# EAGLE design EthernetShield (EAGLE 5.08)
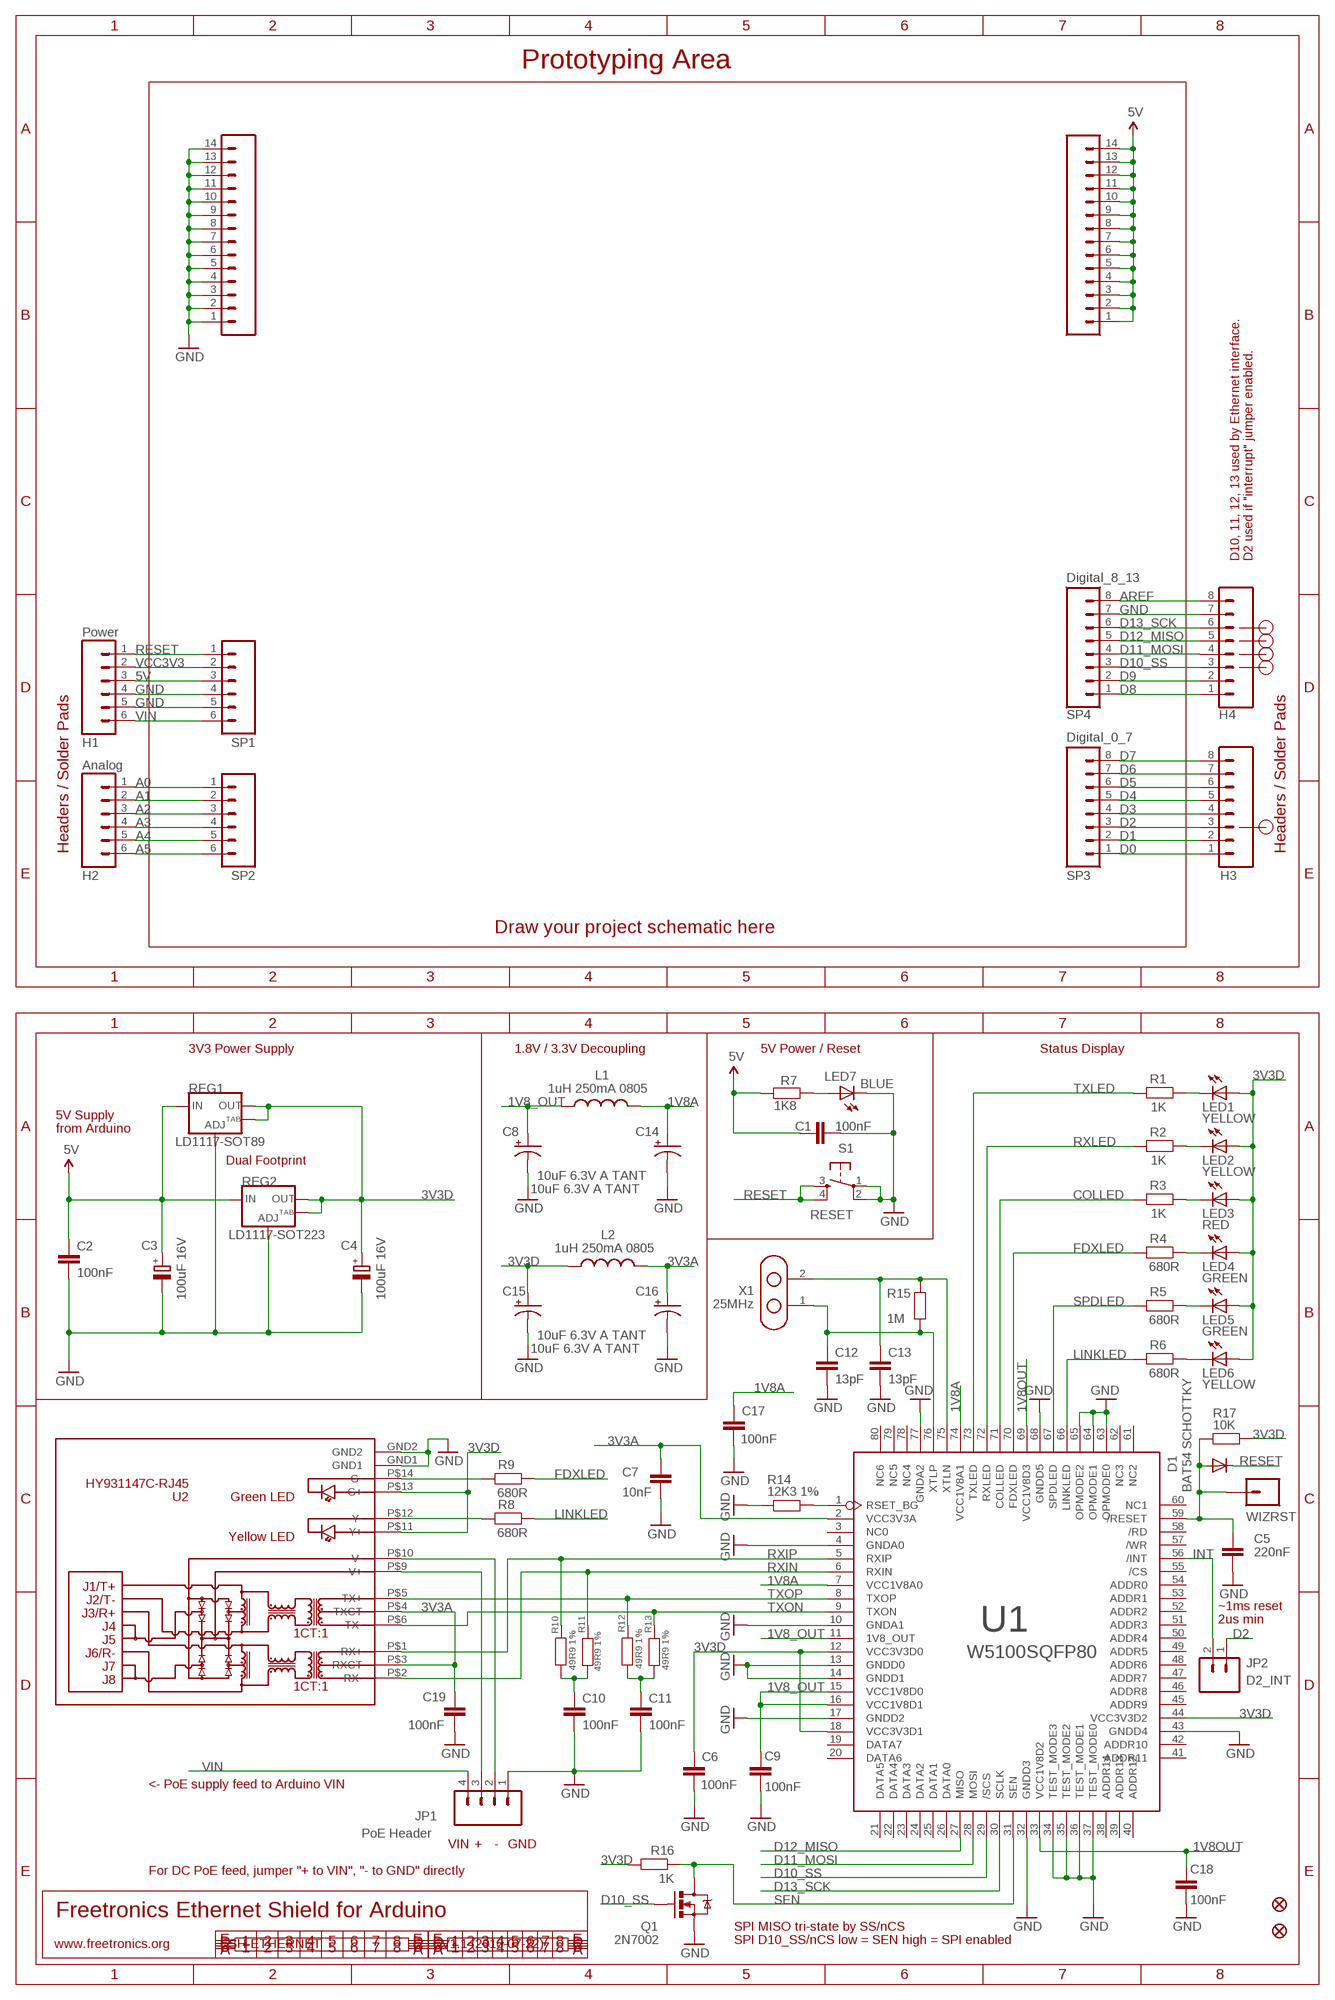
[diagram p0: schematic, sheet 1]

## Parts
C1  100nF  CAP0603  [0603]
C2  100nF  CAP0603  [0603]
C3  100uF 16V  CPOL-EUD  [PANASONIC_D]
C4  100uF 16V  CPOL-EUD  [PANASONIC_D]
C5  220nF  CAP0603  [0603]
C6  100nF  CAP0603  [0603]
C7  10nF  CAP0603  [0603]
C8  10uF 6.3V A TANT  CAP_POL1206  [EIA3216]
C9  100nF  CAP0603  [0603]
C10  100nF  CAP0603  [0603]
C11  100nF  CAP0603  [0603]
C12  13pF  CAP0603  [0603]
C13  13pF  CAP0603  [0603]
C14  10uF 6.3V A TANT  CAP_POL1206  [EIA3216]
C15  10uF 6.3V A TANT  CAP_POL1206  [EIA3216]
C16  10uF 6.3V A TANT  CAP_POL1206  [EIA3216]
C17  100nF  CAP0603  [0603]
C18  100nF  CAP0603  [0603]
C19  100nF  CAP0603  [0603]
D1  BAT54 SCHOTTKY  DIODESOT23  [SOT23-3]
H1  Power  M06SIP  [1X06]
H2  Analog  M06SIP  [1X06]
H3  Digital_0_7  M08  [1X08]
H4  Digital_8_13  M08  [1X08]
JP1  PoE Header  M04PTH  [1X04]
JP2  D2_INT  M02PTH  [1X02]
L1  1uH 250mA 0805  L-USL2012C  [L2012C]
L2  1uH 250mA 0805  L-USL2012C  [L2012C]
LED1  YELLOW  LED0603  [LED-0603]
LED2  YELLOW  LED0603  [LED-0603]
LED3  RED  LED0603  [LED-0603]
LED4  GREEN  LED0603  [LED-0603]
LED5  GREEN  LED0603  [LED-0603]
LED6  YELLOW  LED0603  [LED-0603]
LED7  BLUE  LED0603  [LED-0603]
PADS_5V  M14  [1X14]
PADS_GND  M14  [1X14]
Q1  2N7002  MOSFET-NCHANNELSMD  [SOT23-3]
R1  1K  RESISTOR0603  [0603]
R2  1K  RESISTOR0603  [0603]
R3  1K  RESISTOR0603  [0603]
R4  680R  RESISTOR0603  [0603]
R5  680R  RESISTOR0603  [0603]
R6  680R  RESISTOR0603  [0603]
R7  1K8  RESISTOR0603  [0603]
R8  680R  RESISTOR0603  [0603]
R9  680R  RESISTOR0603  [0603]
R10  49R9 1%  RESISTOR0603  [0603]
R11  49R9 1%  RESISTOR0603  [0603]
R12  49R9 1%  RESISTOR0603  [0603]
R13  49R9 1%  RESISTOR0603  [0603]
R14  12K3 1%  RESISTOR0603  [0603]
R15  1M  RESISTOR0603  [0603]
R16  1K  RESISTOR0603  [0603]
R17  10K  RESISTOR0603  [0603]
REG1  LD1117-SOT89  V_REG_LM1117SOT89  [SOT89]
REG2  LD1117-SOT223  V_REG_LM1117SOT223  [SOT223]
S1  RESET  TAC_SWITCHSMD  [TACTILE_SWITCH_SMD]
SP1  Power  M06SIP  [1X06]
SP2  Analog  M06SIP  [1X06]
SP3  Digital_0_7  M08  [1X08]
SP4  Digital_8_13  M08  [1X08]
U1  W5100SQFP80  [SQFP80]
U2  HY931147C-RJ45  [HY931147C]
U$6  FIDUCIAL1X2.5  [FIDUCIAL-1X2.5]
U$8  FIDUCIAL1X2.5  [FIDUCIAL-1X2.5]
WIZRST  M01PTH  [1X01]
X1  25MHz  XTL_B  [XTL_B]

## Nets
1V8_OUT: C8.A(+) C9.1 L1.1 U1.11(1V8_OUT) U1.15(VCC1V8D0) U1.16(VCC1V8D1)
1V8A: C14.A(+) C17.1 L1.2 U1.7(VCC1V8A0) U1.74(VCC1V8A1)
1V8OUT: C18.1 U1.33(VCC1V8D2) U1.69(VCC1V8D3)
3V3A: C7.1 C16.A(+) C19.1 L2.2 U1.2(VCC3V3A) U2.P$3(RXCT) U2.P$4(TXCT)
3V3D: C4.+ C6.1 C15.A(+) L2.1 LED1.A LED2.A LED3.A LED4.A LED5.A LED6.A R16.2 R17.1 REG1.2(OUT) REG1.4(OUT) REG2.2(OUT) REG2.4(OUT) U1.12(VCC3V3D0) U1.18(VCC3V3D1) U1.44(VCC3V3D2) U2.P$11(Y+) U2.P$13(G+)
5V: C1.1 C2.1 C3.+ H1.3 PADS_5V.1 PADS_5V.2 PADS_5V.3 PADS_5V.4 PADS_5V.5 PADS_5V.6 PADS_5V.7 PADS_5V.8 PADS_5V.9 PADS_5V.10 PADS_5V.11 PADS_5V.12 PADS_5V.13 PADS_5V.14 R7.1 REG1.3(IN) REG2.3(IN) SP1.3
A0: H2.1 SP2.1
A1: H2.2 SP2.2
A2: H2.3 SP2.3
A3: H2.4 SP2.4
A4: H2.5 SP2.5
A5: H2.6 SP2.6
AREF: H4.8 SP4.8
COLLED: R3.2 U1.71(COLLED)
D0: H3.1 SP3.1
D1: H3.2 SP3.2
D2: H3.3 JP2.1 SP3.3
D3: H3.4 SP3.4
D4: H3.5 SP3.5
D5: H3.6 SP3.6
D6: H3.7 SP3.7
D7: H3.8 SP3.8
D8: H4.1 SP4.1
D9: H4.2 SP4.2
D10_SS: H4.3 Q1.1(G) SP4.3 U1.29(/SCS)
D11_MOSI: H4.4 SP4.4 U1.28(MOSI)
D12_MISO: H4.5 SP4.5 U1.27(MISO)
D13_SCK: H4.6 SP4.6 U1.30(SCLK)
FDXLED: R4.2 R9.1 U1.70(FDXLED)
GND: C1.2 C2.2 C3.- C4.- C5.2 C6.2 C7.2 C8.C(-) C9.2 C10.2 C11.2 C12.2 C13.2 C14.C(-) C15.C(-) C16.C(-) C17.2 C18.2 C19.2 H1.4 H1.5 H4.7 JP1.1 LED7.C PADS_GND.1 PADS_GND.2 PADS_GND.3 PADS_GND.4 PADS_GND.5 PADS_GND.6 PADS_GND.7 PADS_GND.8 PADS_GND.9 PADS_GND.10 PADS_GND.11 PADS_GND.12 PADS_GND.13 PADS_GND.14 Q1.2(S) R14.1 REG1.1(ADJ) REG2.1(ADJ) S1.1 S1.2 SP1.4 SP1.5 SP4.7 U1.4(GNDA0) U1.10(GNDA1) U1.13(GNDD0) U1.14(GNDD1) U1.17(GNDD2) U1.32(GNDD3) U1.34(TEST_MODE3) U1.35(TEST_MODE2) U1.36(TEST_MODE1) U1.37(TEST_MODE0) U1.43(GNDD4) U1.63(OPMODE0) U1.64(OPMODE1) U1.65(OPMODE2) U1.68(GNDD5) U1.77(GNDA2) U2.GND1 U2.GND2
INT: JP2.2 U1.56(/INT)
LINKLED: R6.2 R8.1 U1.66(LINKLED)
N$1: C11.1 R12.1 R13.2
N$67: R9.2 U2.P$14(G-)
N$68: JP1.3 U2.P$9(V+)
N$69: JP1.2 U2.P$10(V-)
N$70: C5.1 D1.1(A) R17.2 U1.59(/RESET) WIZRST.1
N$131: LED7.A R7.2
N$321: C10.1 R10.1 R11.2
N$322: R14.2 U1.1(RSET_BG)
N$323: LED5.C R5.1
N$325: LED6.C R6.1
N$327: LED4.C R4.1
N$328: LED3.C R3.1
N$329: LED2.C R2.1
N$330: LED1.C R1.1
N$332: R8.2 U2.P$12(Y-)
RESET: D1.3(C) H1.1 S1.3 S1.4 SP1.1
RXIN: R11.1 U1.6(RXIN) U2.P$2(RX-)
RXIP: R10.2 U1.5(RXIP) U2.P$1(RX+)
RXLED: R2.2 U1.72(RXLED)
SEN: Q1.3(D) R16.1 U1.31(SEN)
SPDLED: R5.2 U1.67(SPDLED)
TXLED: R1.2 U1.73(TXLED)
TXON: R13.1 U1.9(TXON) U2.P$6(TX-)
TXOP: R12.2 U1.8(TXOP) U2.P$5(TX+)
VCC3V3: H1.2 SP1.2
VIN: H1.6 JP1.4 SP1.6
XTLN: C13.1 R15.2 U1.75(XTLN) X1.2
XTLP: C12.1 R15.1 U1.76(XTLP) X1.1
Unconnected: U1.3(NC0) U1.19(DATA7) U1.20(DATA6) U1.21(DATA5) U1.22(DATA4) U1.23(DATA3) U1.24(DATA2) U1.25(DATA1) U1.26(DATA0) U1.38(ADDR14) U1.39(ADDR13) U1.40(ADDR12) U1.41(ADDR11) U1.42(ADDR10) U1.45(ADDR9) U1.46(ADDR8) U1.47(ADDR7) U1.48(ADDR6) U1.49(ADDR5) U1.50(ADDR4) U1.51(ADDR3) U1.52(ADDR2) U1.53(ADDR1) U1.54(ADDR0) U1.55(/CS) U1.57(/WR) U1.58(/RD) U1.60(NC1) U1.61(NC2) U1.62(NC3) U1.78(NC4) U1.79(NC5) U1.80(NC6)

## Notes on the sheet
- Prototyping Area
- D10, 11, 12, 13 used by Ethernet interface. | D2 used if "interrupt" jumper enabled.
- Headers / Solder Pads | Headers / Solder Pads
- Draw your project schematic here
- 3V3 Power Supply | 1.8V / 3.3V Decoupling | 5V Power / Reset | Status Display
- 5V Supply
- from Arduino
- Dual Footprint
- ~1ms reset
- 2us min
- <- PoE supply feed to Arduino VIN
- VIN | + | - | GND
- For DC PoE feed, jumper "+ to VIN", "- to GND" directly
- Freetronics Ethernet Shield for Arduino
- SPI MISO tri-state by SS/nCS
- SPI D10_SS/nCS low = SEN high = SPI enabled
- www.freetronics.org | SH-ETHERNET | V1.1 (2010-07-22)

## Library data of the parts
C1 C2 C5-C7 C9-C13 C17-C19 = freetronics:CAP: Capacitor
C3 C4 = rcl:CPOL-EU: POLARIZED CAPACITOR, European symbol
C8 C14-C16 = freetronics:CAP_POL: Capacitor Polarized
D1 = freetronics:DIODE: Diode
H1 H2 SP1 SP2 = freetronics:M06: Header 6 Standard 6-pin 0.1" header. Use with straight break away headers (SKU : PRT-00116), right angle break away headers (PRT-00553), swiss pins (PRT-00743), machine pins (PRT-00117), and female headers (PRT-00115). Molex polarized connector foot print use with SKU : PRT-08094 with associated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
H3 H4 SP3 SP4 = freetronics:M08: Header 8 Standard 8-pin 0.1" header. Use with straight break away headers (SKU : PRT-00116), right angle break away headers (PRT-00553), swiss pins (PRT-00743), machine pins (PRT-00117), and female headers (PRT-00115).
JP1 = freetronics:M04: Header 4 Standard 4-pin 0.1" header. Use with straight break away headers (SKU : PRT-00116), right angle break away headers (PRT-00553), swiss pins (PRT-00743), machine pins (PRT-00117), and female headers (PRT-00115). Molex polarized connector foot print use with SKU : PRT-08231 with associated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
JP2 = freetronics:M02: Header 2
L1 L2 = rcl:L-US: INDUCTOR, American symbol
LED1-LED7 = freetronics:LED: LEDs
PADS_5V PADS_GND = freetronics:M14: Header 14 Standard 14-pin 0.1" header. Use with straight break away headers (SKU : PRT-00116), right angle break away headers (PRT-00553), swiss pins (PRT-00743), machine pins (PRT-00117), and female headers (PRT-00115).
Q1 = freetronics:MOSFET-NCHANNEL
R1-R17 = freetronics:RESISTOR: Resistor
REG1 REG2 = freetronics:V_REG_LM1117: Voltage Regulator LD1117 Adjustable low-dropout voltage regulator available in SOT89 and SOT223 SMT packages.
S1 = freetronics:TAC_SWITCH: Momentary Switch Button commonly used for reset or general input. Spark Fun Electronics SKU : COM-00097
U1 = freetronics-marc:W5100: WIZnet W5100
U2 = freetronics-jon:HY931147C
U$6 U$8 = freetronics:FIDUCIAL: Fiducial Alignment Points
WIZRST = freetronics:M01: Header 1
X1 = CPT_CJ:XTL_B

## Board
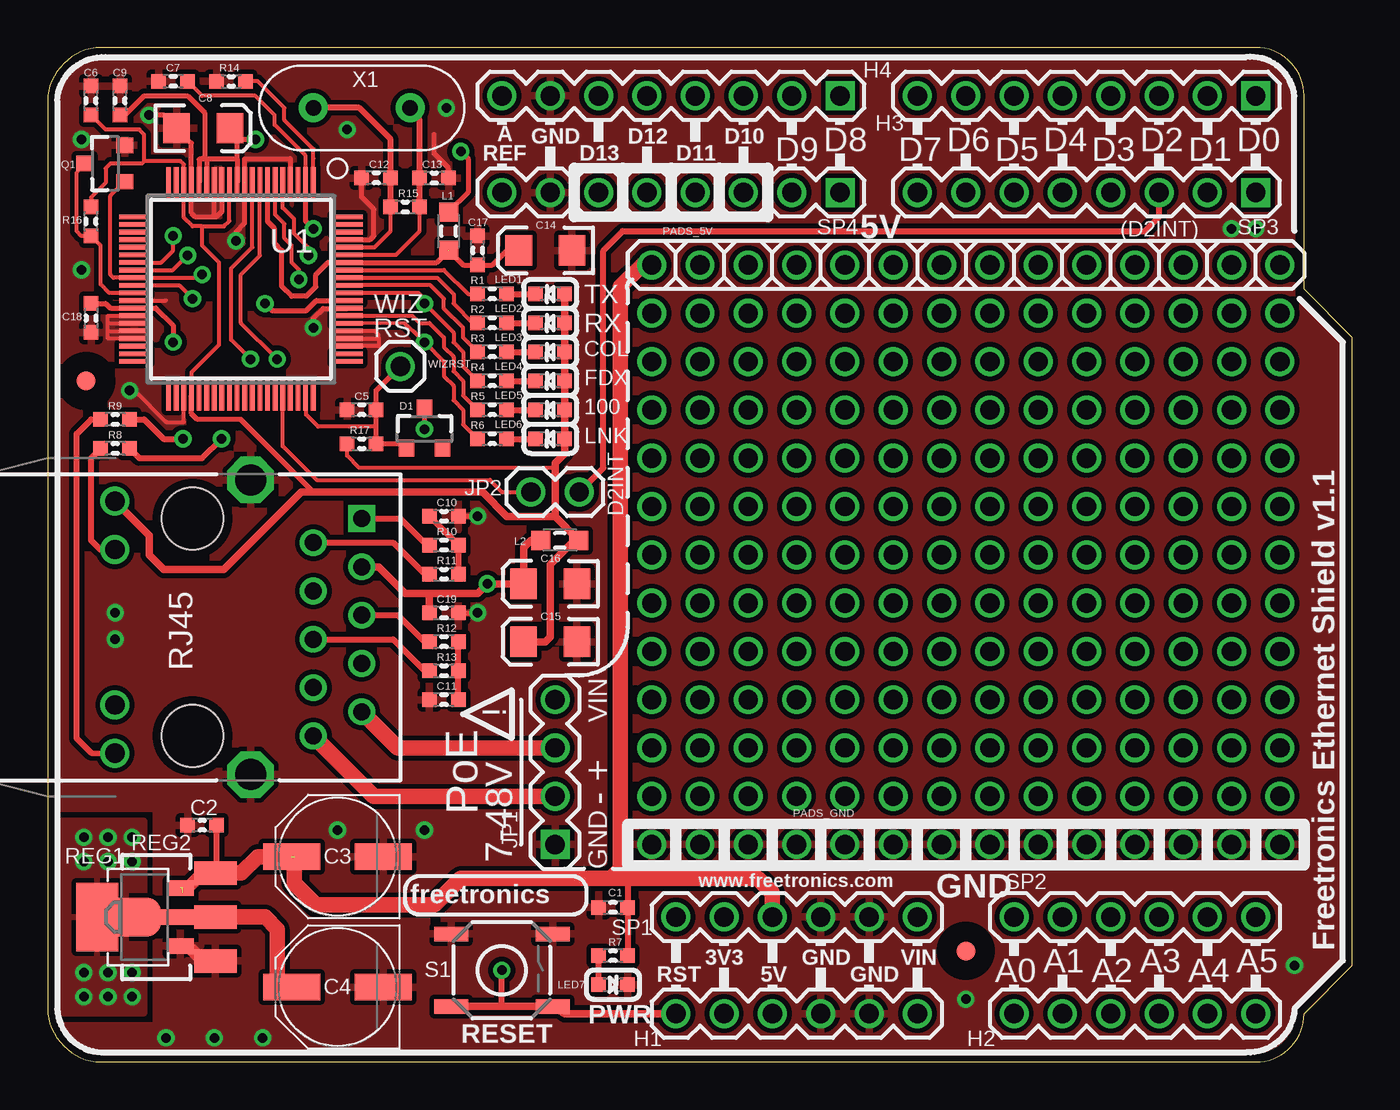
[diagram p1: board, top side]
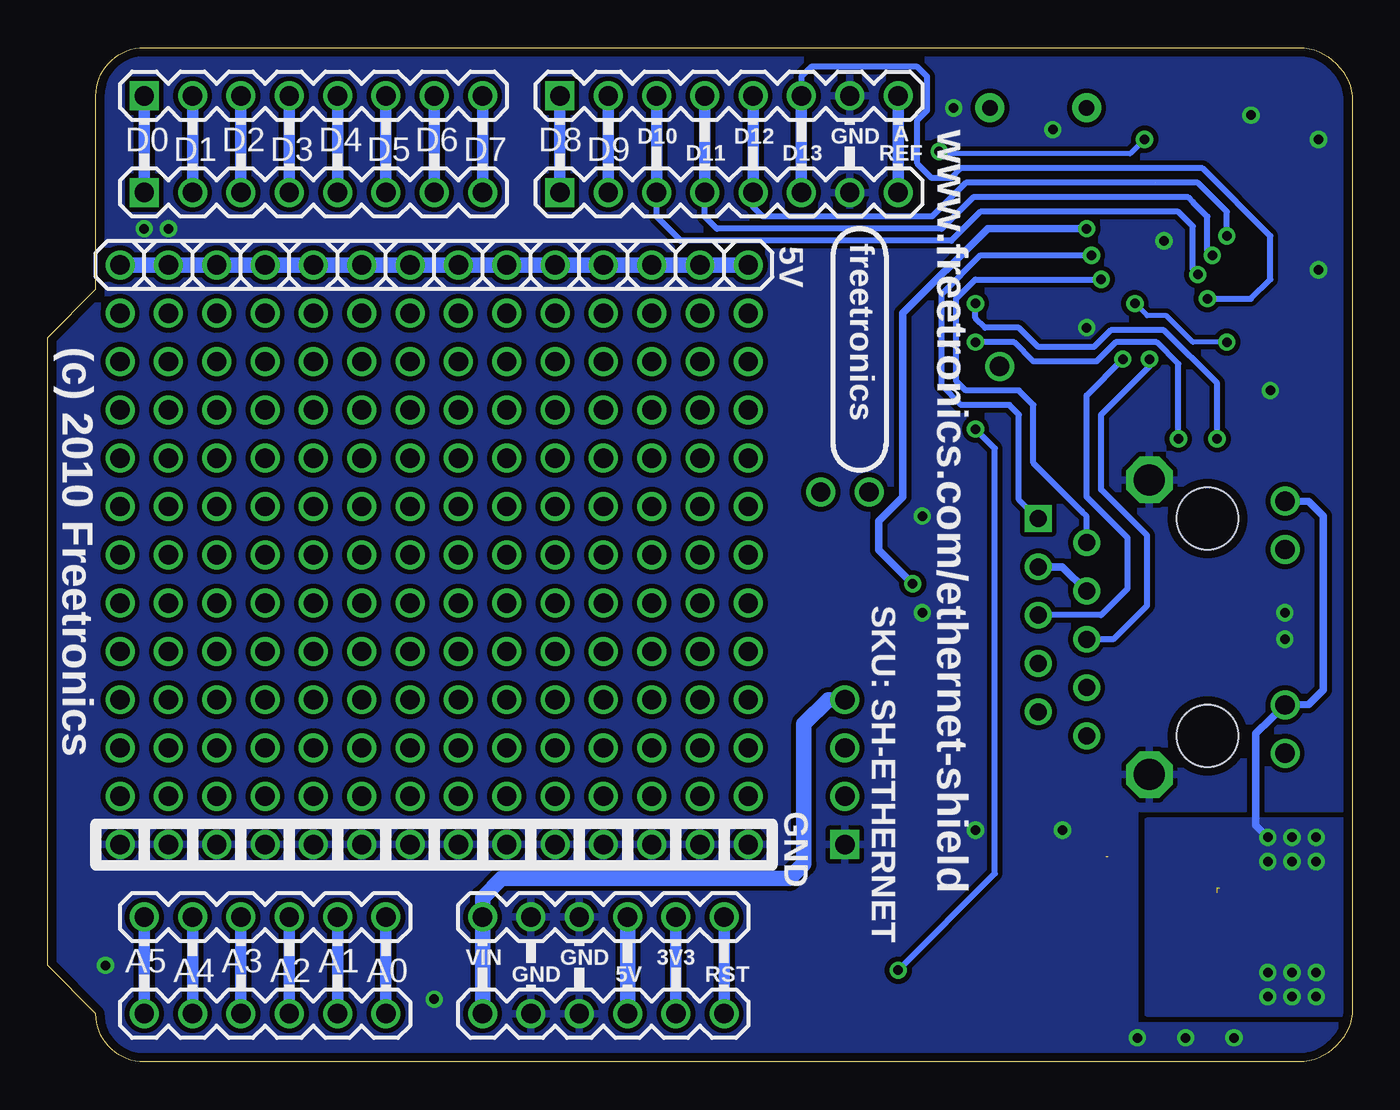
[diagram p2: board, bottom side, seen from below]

Size 68.58 x 53.34 mm. Coordinates in mm from the lower left corner, seen from the top.
Outline: 0,2.54 arc74 2.54,0 63.5,0 arc90 66.04,2.54 68.58,5.08 68.58,38.1 66.04,40.64 66.04,50.8 arc90 63.5,53.34 2.54,53.34 arc74 0,50.8 0,2.54
Copper layers (1*16): Top 0.035mm / dielectric 1.5mm / Bottom 0.035mm
Design rules "default *": minimum track width 8mil, minimum drill 18mil, track to track 10mil, track to pad 10mil, pad to pad 10mil, via to via 10mil, smd to smd 8mil, copper to edge 18mil, drill to drill 8mil, minimum pad ring 10mil, minimum via ring 8mil, stop-mask expansion 4mil, vias tented up to drill 25mil, thermal gap 10mil
tRestrict: area 1,34.8 to 3,36.8; area 47.2,4.8 to 49.3,6.9

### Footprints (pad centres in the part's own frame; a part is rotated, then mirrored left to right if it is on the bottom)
0603 = smd 0.762 x 0.762: 1 -0.762,0; 2 0.762,0
PANASONIC_D = smd 3 x 1.4: + 2.4,0; - -2.4,0
EIA3216 = smd 1.4 x 1.6: A 1.4,0; C -1.4,0
SOT23-3 = smd 0.8 x 0.9: 1 -0.95,-1; 2 0.95,-1; 3 0,1.1
1X06 = drill 1.016 round: 1 0,0; 2 2.54,0; 3 5.08,0; 4 7.62,0; 5 10.16,0; 6 12.7,0
1X08 = drill 1.016 square: 1 0,0 | drill 1.016 round: 2 2.54,0; 3 5.08,0; 4 7.62,0; 5 10.16,0; 6 12.7,0; 7 15.24,0; 8 17.78,0
1X04 = drill 1.016 square: 1 0,0 | drill 1.016 round: 2 2.54,0; 3 5.08,0; 4 7.62,0
1X02 = drill 1.016 round: 1 0,0; 2 2.54,0
L2012C = smd 1 x 1: 1 -1,0; 2 1,0
LED-0603 = smd 0.762 x 0.762: A -0.762,0; C 0.762,0
1X14 = drill 1.016 round: 1 0,0; 2 2.54,0; 3 5.08,0; 4 7.62,0; 5 10.16,0; 6 12.7,0; 7 15.24,0; 8 17.78,0; 9 20.32,0; 10 22.86,0; 11 25.4,0; 12 27.94,0; 13 30.48,0; 14 33.02,0
SOT89 = smd 0.8 x 1.4: 1 -1.524,-1.905; 3 1.524,-1.905 | smd 0.8 x 1.9: 2 0,-1.651 | smd 2.032 x 3.65: 4 0,0.94
SOT223 = smd 1.219 x 2.235: 1 -2.311,-3.099; 2 0,-3.099; 3 2.311,-3.099 | smd 3.6 x 2.2: 4 0,3.099
TACTILE_SWITCH_SMD = smd 1.778 x 0.762: 1 -2.667,1.905; 2 2.667,1.905; 3 -2.667,-1.905; 4 2.667,-1.905
SQFP80 = smd 1.6 x 0.25: 1 -5.6,3.8; 2 -5.6,3.4; 3 -5.6,3; 4 -5.6,2.6; 5 -5.6,2.2; 6 -5.6,1.8; 7 -5.6,1.4; 8 -5.6,1; 9 -5.6,0.6; 10 -5.6,0.2; 11 -5.6,-0.2; 12 -5.6,-0.6; 13 -5.6,-1; 14 -5.6,-1.4; 15 -5.6,-1.8; 16 -5.6,-2.2; 17 -5.6,-2.6; 18 -5.6,-3; 19 -5.6,-3.4; 20 -5.6,-3.8; 41 5.6,-3.8; 42 5.6,-3.4; 43 5.6,-3; 44 5.6,-2.6; 45 5.6,-2.2; 46 5.6,-1.8; 47 5.6,-1.4; 48 5.6,-1; 49 5.6,-0.6; 50 5.6,-0.2; 51 5.6,0.2; 52 5.6,0.6; 53 5.6,1; 54 5.6,1.4; 55 5.6,1.8; 56 5.6,2.2; 57 5.6,2.6; 58 5.6,3; 59 5.6,3.4; 60 5.6,3.8 | smd 0.25 x 1.6: 21 -3.8,-5.6; 22 -3.4,-5.6; 23 -3,-5.6; 24 -2.6,-5.6; 25 -2.2,-5.6; 26 -1.8,-5.6; 27 -1.4,-5.6; 28 -1,-5.6; 29 -0.6,-5.6; 30 -0.2,-5.6; 31 0.2,-5.6; 32 0.6,-5.6; 33 1,-5.6; 34 1.4,-5.6; 35 1.8,-5.6; 36 2.2,-5.6; 37 2.6,-5.6; 38 3,-5.6; 39 3.4,-5.6; 40 3.8,-5.6; 61 3.8,5.6; 62 3.4,5.6; 63 3,5.6; 64 2.6,5.6; 65 2.2,5.6; 66 1.8,5.6; 67 1.4,5.6; 68 1,5.6; 69 0.6,5.6; 70 0.2,5.6; 71 -0.2,5.6; 72 -0.6,5.6; 73 -1,5.6; 74 -1.4,5.6; 75 -1.8,5.6; 76 -2.2,5.6; 77 -2.6,5.6; 78 -3,5.6; 79 -3.4,5.6; 80 -3.8,5.6
HY931147C = drill 1.63 octagon: GND1 3.05,7.745; GND2 3.05,-7.745 | drill 0.9 square: P$1 8.89,5.715 | drill 0.9 round: P$2 6.35,4.445; P$3 8.89,3.175; P$4 6.35,1.905; P$5 8.89,0.635; P$6 6.35,-0.635; P$7 8.89,-1.905; P$8 6.35,-3.175; P$9 8.89,-4.445; P$10 6.35,-5.715 | drill 1.016 round: P$11 -4.08,6.625; P$12 -4.08,4.085; P$13 -4.08,-4.085; P$14 -4.08,-6.625 | hole 3.25: 0,5.715; 0,-5.715
FIDUCIAL-1X2.5 = smd 1 x 1: 1 0,0
1X01 = drill 1.016 round: 1 0,0
XTL_B = drill 0.813 pad 1.524 round: 1 0,2.54; 2 0,-2.54

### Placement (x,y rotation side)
C1  29.72,8.13 180 top
C2  8.13,12.45 180 top
C3  15.24,10.79 180 top
C4  15.24,3.94 180 top
C5  16.51,34.29 180 top
C6  2.29,50.55 90 top
C7  6.6,51.56 180 top
C8  8.18,49.1 0 top
C9  3.81,50.55 90 top
C10  20.83,28.7 0 top
C11  20.83,19.05 180 top
C12  17.27,46.48 180 top
C13  20.32,46.48 0 top
C14  26.16,42.67 180 top
C15  26.42,22.1 180 top
C16  26.42,25.15 180 top
C17  22.61,42.67 90 top
C18  2.29,39.12 270 top
C19  20.83,23.62 0 top
D1  19.81,33.27 0 top
H1  33.02,2.54 0 top
H2  50.8,2.54 0 top
H3  63.5,50.8 180 top
H4  41.66,50.8 180 top
JP1  26.67,11.43 90 top
JP2  27.94,29.97 180 top
L1  21.08,43.69 270 top
L2  26.92,27.43 180 top
LED1  26.42,40.39 180 top
LED2  26.42,38.86 180 top
LED3  26.42,37.34 180 top
LED4  26.42,35.81 180 top
LED5  26.42,34.29 180 top
LED6  26.42,32.77 180 top
LED7  29.72,4.06 0 top
PADS_5V  31.75,41.91 0 top
PADS_GND  31.75,11.43 0 top
Q1  3.05,47.24 90 top
R1  23.37,40.39 180 top
R2  23.37,38.86 180 top
R3  23.37,37.34 180 top
R4  23.37,35.81 180 top
R5  23.37,34.29 180 top
R6  23.37,32.77 180 top
R7  29.72,5.59 180 top
R8  3.56,32.26 180 top
R9  3.56,33.78 180 top
R10  20.83,27.18 180 top
R11  20.83,25.65 0 top
R12  20.83,22.1 180 top
R13  20.83,20.57 0 top
R14  9.65,51.56 0 top
R15  18.8,44.96 0 top
R16  2.29,44.2 90 top
R17  16.51,32.51 0 top
REG1  5.08,7.62 90 top
REG2  5.71,7.62 90 top
S1  23.88,4.83 0 top
SP1  33.02,7.62 0 top
SP2  50.8,7.62 0 top
SP3  63.5,45.72 180 top
SP4  41.66,45.72 180 top
U1  10.16,40.64 270 top
U2  7.62,22.86 0 top
U$6  2.03,35.81 0 top
U$8  48.26,5.84 0 top
WIZRST  18.54,36.58 0 top
X1  16.51,50.16 90 top

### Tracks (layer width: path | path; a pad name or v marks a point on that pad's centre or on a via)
1V8_OUT  (via drill 0.5)
  Top 0.254: C9.1 4.06,49.78 5.08,50.8 7.37,50.8 8.26,49.91 8.26,47.47 | 8.26,47.47 7.96,47.46 U1.16 | 9.96,47.5 U1.11 | 9.96,47.5 9.96,48.84 C8.A 10.16,48.51 v10.92,48.51 | 8.23,47.5 8.36,47.5 | 8.36,47.5 9.96,47.5 | U1.15 8.36,47.5 | L1.1 21.08,44.7 22.1,45.72 22.1,47.5 v21.72,47.88 | 8.26,47.47 8.23,47.5 | 8.23,47.5 8.13,47.5
  Bottom 0.254: v10.92,48.51 11.68,47.75 21.59,47.75 v21.72,47.88
1V8A  (1 unrouted)
  Top 0.254: C14.A 24.13,42.67 23.37,41.91 C17.1 21.84,41.91 21.08,42.67 20.45,42.04 U1.74 14.73,42.04 14.1,41.4 14.1,40.77 13.59,40.26 12.83,40.26 12.32,40.77 12.32,42.67 11.94,43.05 11.94,43.81 11.56,44.19 U1.7
1V8OUT  (via drill 0.5)
  Top 0.254: C18.1 3.05,39.88 3.29,39.64 U1.33 5.69,39.65 6.6,38.73 v6.6,37.85 | U1.69 14.13,40.04 13.59,39.5 11.81,39.5 v11.43,39.88
  Bottom 0.254: v11.43,39.88 10.79,39.24 9.78,39.24 8.38,37.85 v6.6,37.85
3V3A  (via drill 0.5)
  Top 0.203: U1.2 13.56,46.27 13.56,47.65 11.94,49.28 11.94,49.78 10.92,50.8 8.13,50.8 C7.1
  Top 0.254: U1.2 13.56,44.22 v13.97,43.81
  Top 0.406: L2.2 25.4,27.43 25.02,27.05 C16.A v23.11,25.15 22.61,24.64 20.07,24.64 | U2.P$3 17.4,26.04 18.8,24.64 20.07,24.64 | 20.07,24.64 C19.1
  Bottom 0.406: U2.P$4 15.24,26.04 U2.P$3 | v13.97,43.81 19.18,43.81 23.62,39.37 23.62,29.72 24.89,28.45 24.89,26.92 v23.11,25.15
3V3D  (via drill 0.5)
  Top 0.203: U1.44 7.57,36.22 7.57,36.27 9.02,37.72 9.02,42.04 8.13,42.93 8.13,43.94 | C6.1 3.05,49.02 4.83,49.02 5.08,48.77 5.08,47.37 | 5.08,47.37 6.99,47.37 7.16,47.2 U1.18 7.16,44.4 7.62,43.94 8.13,43.94 | U1.12 9.55,44.22 9.27,43.94 8.13,43.94 | R16.2 2.29,45.47 3.05,46.23 3.05,46.99 3.3,47.24 4.95,47.24 5.08,47.37 | R17.1 15.75,31.88 16.38,31.24 26.67,31.24
  Top 0.254: 13.97,29.97 10.16,33.78 7.87,33.78 7.56,34.1 U1.44
  Top 0.406: LED1.A LED2.A LED3.A LED4.A LED5.A LED6.A 27.18,32 26.67,31.5 26.67,31.24 26.67,28.69 | REG1.4 REG1.2 REG2.2 | C15.A 26.16,22.1 26.42,22.35 26.42,26.16 27.69,27.43 L2.1 26.67,28.69 | U2.P$11 5.33,27.69 5.33,26.67 6.1,25.91 9.27,25.91 13.34,29.97 13.97,29.97 22.86,29.97 24.15,28.69 26.67,28.69
  Top 0.813: C4.+ 12.06,3.81 12.06,6.99 11.43,7.62 REG2.2
  Bottom 0.406: v4.45,11.81 5.08,12.45 5.08,17.27 U2.P$13 2.29,18.8 1.52,19.56 1.52,28.7 2.29,29.46 U2.P$11
  other vias: 1.91,11.81 1.91,3.43 4.45,3.43 1.91,10.54 1.91,4.7 4.45,10.54 4.45,4.7 3.17,3.43 3.17,4.7 3.17,10.54 3.17,11.81
  pour Top: 0,12.7 5.08,12.7 5.08,2.54 0,2.54
  pour Bottom: 0,12.7 10.79,12.7 10.79,2.54 0,2.54
5V  (3 unrouted)
  Top 0.254: 7.11,8.89 7.37,8.89 8.13,9.65 | 7.11,9.14 7.87,9.91
  Top 0.305: C2.1 8.89,10.41 8.81,10.41 REG2.3 | 30.48,9.65 C1.1 R7.1
  Top 0.406: REG1.3 REG2.3
  Top 0.61: 31.24,9.65 30.48,10.41 | 29.46,9.65 30.23,10.41
  Top 0.813: REG2.3 10.19,9.93 11.05,10.79 C3.+ | SP1.3 38.1,8.89 37.34,9.65 31.24,9.65 30.48,9.65 30.1,9.65 | 30.1,9.65 29.46,9.65 21.72,9.65 20.32,8.26 14.1,8.26 12.95,9.4 12.95,10.79 | 30.1,9.65 30.1,40.77 31.24,41.91 PADS_5V.1
  Bottom 0.813: SP1.3 H1.3 | PADS_5V.1 PADS_5V.2 PADS_5V.3 PADS_5V.4 PADS_5V.5 PADS_5V.6 PADS_5V.7 PADS_5V.8 PADS_5V.9 PADS_5V.10 PADS_5V.11 PADS_5V.12 PADS_5V.13 PADS_5V.14
A0
  Bottom 0.61: H2.1 SP2.1
A1
  Bottom 0.61: H2.2 SP2.2
A2
  Bottom 0.61: H2.3 SP2.3
A3
  Bottom 0.61: H2.4 SP2.4
A4
  Bottom 0.61: H2.5 SP2.5
A5
  Bottom 0.61: H2.6 SP2.6
AREF
  Bottom 0.61: SP4.8 H4.8
COLLED
  Top 0.203: U1.71 20.12,40.84 20.83,40.13 20.83,39.62 21.84,38.61 21.84,38.1 R3.2
D0
  Bottom 0.61: SP3.1 H3.1
D1
  Bottom 0.61: SP3.2 H3.2
D2
  Top 0.305: JP2.1 29.21,31.24 29.21,42.67 30.23,43.69 57.66,43.69 58.42,44.45 SP3.3
  Bottom 0.61: SP3.3 H3.3
D3
  Bottom 0.61: SP3.4 H3.4
D4
  Bottom 0.61: SP3.5 H3.5
D5
  Bottom 0.61: SP3.6 H3.6
D6
  Bottom 0.61: SP3.7 H3.7
D7
  Bottom 0.61: SP3.8 H3.8
D8
  Bottom 0.61: SP4.1 H4.1
D9
  Bottom 0.61: SP4.2 H4.2
D10_SS  (via drill 0.5)
  Top 0.203: v8.13,41.4 7.9,41.24 U1.29 3.46,41.24 3.3,41.4 3.3,45.55 Q1.1
  Bottom 0.305: SP4.3 36.58,44.45 35.31,43.18 21.08,43.18 19.56,44.7 9.14,44.7 8.38,43.94 8.38,41.66 v8.13,41.4
  Bottom 0.61: SP4.3 H4.3
D11_MOSI  (via drill 0.5)
  Top 0.203: U1.28 6.58,41.64 v7.37,42.42
  Bottom 0.305: SP4.4 34.04,44.45 33.4,43.81 21.59,43.81 19.94,45.47 8.64,45.47 8.38,45.21 7.62,44.45 7.62,42.67 v7.37,42.42
  Bottom 0.61: SP4.4 H4.4
D12_MISO  (via drill 0.5)
  Top 0.203: U1.27 5.97,42.04 6.6,42.67 v6.6,43.43
  Bottom 0.305: SP4.5 31.5,44.96 30.99,44.45 22.1,44.45 20.32,46.23 8.13,46.23 6.6,44.7 v6.6,43.43
  Bottom 0.61: SP4.5 H4.5
D13_SCK  (via drill 0.5)
  Top 0.203: U1.30 6.91,40.84 v7.62,40.13
  Bottom 0.305: v7.62,40.13 5.33,40.13 4.32,41.15 4.32,43.43 7.87,46.99 20.57,46.99 21.08,46.48 22.1,46.48 22.86,47.24 22.86,49.53 22.35,50.04 22.35,51.82 22.86,52.32 28.45,52.32 28.96,51.82 H4.6
  Bottom 0.61: H4.6 SP4.6
FDXLED  (via drill 0.5)
  Top 0.203: U1.70 19.51,40.44 19.81,40.13 v19.81,39.88 21.34,38.35 21.34,37.85 21.84,37.34 21.84,36.58 R4.2
  Top 0.305: R9.1 5.08,33.78 6.1,32.77 v7.11,32.77
  Bottom 0.305: v7.11,32.77 7.11,35.69 9.91,38.48 12.7,38.48 13.59,37.59 16.51,37.59 17.53,38.61 19.3,38.61 19.81,39.12 v19.81,39.88
GND  (via drill 0.5)  (1 unrouted)
  Top 0.203: U1.32 6.22,40.04 | U1.43 7.16,33.66 6.22,33.66 4.57,35.31 v4.32,35.31 | U1.37 3.17,38.04 3.17,38.44 | U1.34 3.17,39.24 3.17,38.84 | 3.17,38.84 U1.35 | 3.17,38.44 U1.36 | 3.17,38.44 3.17,38.84 | U1.63 17.4,37.64 17.4,38.1 | 17.4,38.1 17.4,38.23 17.19,38.44 U1.65 | U1.64 17.34,38.04 arc90 17.4,38.1
  Top 0.254: U1.4 12.76,47.44 12.75,47.5 10.36,47.49 U1.10 | U1.77 16.95,43.24 17.14,43.43 17.14,44.83 16.51,45.47 C12.2 | v5.33,49.78 6.09,49.78 C8.C 7.56,48.32 U1.17 7.56,44.64 7.75,44.45 8.76,44.45 | U1.13 9.17,46.22 9.17,44.73 8.89,44.45 8.76,44.45 | U1.14 8.76,46.21 8.76,44.45 | 7.37,6.1 7.11,6.1 | 7.37,6.1 7.62,6.1 8.13,5.59 | 7.37,6.1 7.37,5.84 7.87,5.33 | C10.2 v22.61,28.7 | C19.2 v22.61,23.62 | 9.91,43.43 v9.91,43.18 9.91,43.64 10.36,44.09 U1.10 | C13.2 21.08,46.99 20.32,47.75 20.32,48.77 | U1.68 15.74,39.62 14.48,39.62 13.97,39.12 v13.97,38.61
  other vias: 8.76,1.27 6.22,1.27 11.3,1.27 65.53,5.08 48.26,3.3 15.24,12.19 15.75,49.02 1.78,48.51 1.78,41.66 20.95,50.16 63.5,43.81 62.23,43.81 3.56,23.62 3.56,22.23 19.81,12.19
  pour Bottom: 0,50.8 arc-74 2.54,53.34 63.5,53.34 arc-74 66.04,50.8 66.04,40.64 68.58,38.1 68.58,5.08 66.04,2.54 arc-74 63.5,0 2.54,0 arc-74 0,1.91 11.43,1.91 11.43,13.34 0,13.34
  pour Top: 0,50.8 arc-74 2.54,53.34 63.5,53.34 arc-74 66.04,50.8 66.04,40.64 68.58,38.1 68.58,5.08 66.04,2.54 arc-74 63.5,0 2.54,0 arc-74 0,1.91 5.71,1.91 5.71,13.34 0,13.34
INT
  Top 0.203: U1.56 12.36,32.38 14.13,30.61 23.24,30.61 23.88,29.97 JP2.2
LINKLED  (via drill 0.5)
  Top 0.203: U1.66 18.77,38.84 19.3,38.35 v19.81,37.85 20.83,36.83 20.83,36.07 21.34,35.56 21.34,34.8 21.84,34.29 21.84,33.53 R6.2
  Top 0.305: R8.1 4.83,31.75 8.13,31.75 v9.14,32.77
  Bottom 0.305: v9.14,32.77 9.14,36.7 10.29,37.85 12.45,37.85 13.46,36.83 16.76,36.83 17.78,37.85 v19.81,37.85 20.07,37.85
N$1
  Top 0.305: R12.1 R13.2 C11.1
N$3  (via drill 1.02)
  other vias: 36.83,13.97
N$4  (via drill 1.02)
  other vias: 34.29,13.97
N$5  (via drill 1.02)
  other vias: 59.69,13.97
N$8  (via drill 1.02)
  other vias: 54.61,13.97
N$9  (via drill 1.02)
  other vias: 52.07,13.97
N$10  (via drill 1.02)
  other vias: 49.53,13.97
N$11  (via drill 1.02)
  other vias: 46.99,13.97
N$12  (via drill 1.02)
  other vias: 44.45,13.97
N$13  (via drill 1.02)
  other vias: 41.91,13.97
N$14  (via drill 1.02)
  other vias: 39.37,13.97
N$15  (via drill 1.02)
  other vias: 31.75,13.97
N$16  (via drill 1.02)
  other vias: 39.37,21.59
N$17  (via drill 1.02)
  other vias: 54.61,24.13
N$18  (via drill 1.02)
  other vias: 31.75,21.59
N$19  (via drill 1.02)
  other vias: 36.83,16.51
N$20  (via drill 1.02)
  other vias: 34.29,16.51
N$21  (via drill 1.02)
  other vias: 31.75,16.51
N$22  (via drill 1.02)
  other vias: 59.69,16.51
N$23  (via drill 1.02)
  other vias: 57.15,16.51
N$24  (via drill 1.02)
  other vias: 54.61,16.51
N$25  (via drill 1.02)
  other vias: 52.07,16.51
N$26  (via drill 1.02)
  other vias: 49.53,16.51
N$27  (via drill 1.02)
  other vias: 46.99,16.51
N$28  (via drill 1.02)
  other vias: 44.45,16.51
N$29  (via drill 1.02)
  other vias: 41.91,16.51
N$30  (via drill 1.02)
  other vias: 39.37,16.51
N$31  (via drill 1.02)
  other vias: 36.83,21.59
N$32  (via drill 1.02)
  other vias: 44.45,21.59
N$33  (via drill 1.02)
  other vias: 57.15,24.13
N$34  (via drill 1.02)
  other vias: 36.83,19.05
N$35  (via drill 1.02)
  other vias: 34.29,19.05
N$36  (via drill 1.02)
  other vias: 31.75,19.05
N$37  (via drill 1.02)
  other vias: 36.83,24.13
N$38  (via drill 1.02)
  other vias: 59.69,19.05
N$39  (via drill 1.02)
  other vias: 57.15,19.05
N$40  (via drill 1.02)
  other vias: 54.61,19.05
N$41  (via drill 1.02)
  other vias: 52.07,19.05
N$42  (via drill 1.02)
  other vias: 49.53,19.05
N$43  (via drill 1.02)
  other vias: 46.99,19.05
N$44  (via drill 1.02)
  other vias: 44.45,19.05
N$45  (via drill 1.02)
  other vias: 41.91,19.05
N$46  (via drill 1.02)
  other vias: 39.37,19.05
N$47  (via drill 1.02)
  other vias: 57.15,13.97
N$48  (via drill 1.02)
  other vias: 44.45,24.13
N$49  (via drill 1.02)
  other vias: 57.15,21.59
N$50  (via drill 1.02)
  other vias: 34.29,26.67
N$51  (via drill 1.02)
  other vias: 34.29,24.13
N$52  (via drill 1.02)
  other vias: 34.29,21.59
N$56  (via drill 1.02)
  other vias: 54.61,21.59
N$57  (via drill 1.02)
  other vias: 52.07,21.59
N$58  (via drill 1.02)
  other vias: 49.53,21.59
N$59  (via drill 1.02)
  other vias: 46.99,21.59
N$62  (via drill 1.02)
  other vias: 36.83,26.67
N$67
  Top 0.305: U2.P$14 2.29,16.26 1.52,17.02 1.52,33.02 2.29,33.78 R9.2
N$68
  Top 0.813: U2.P$9 18.41,16.51 JP1.3
N$69
  Top 0.813: JP1.2 17.14,13.97 U2.P$10
N$70
  Top 0.203: 17.27,33.4 14.22,33.4 13.59,34.04 13.59,35.01 U1.59
  Top 0.254: D1.1 18.85,32.51 R17.2 17.27,33.4 C5.1 17.27,35.31 WIZRST.1
N$74  (via drill 1.02)
  other vias: 49.53,24.13
N$75  (via drill 1.02)
  other vias: 31.75,26.67
N$81  (via drill 1.02)
  other vias: 31.75,24.13
N$82  (via drill 1.02)
  other vias: 36.83,29.21
N$83  (via drill 1.02)
  other vias: 34.29,29.21
N$84  (via drill 1.02)
  other vias: 31.75,29.21
N$85  (via drill 1.02)
  other vias: 36.83,31.75
N$86  (via drill 1.02)
  other vias: 59.69,26.67
N$87  (via drill 1.02)
  other vias: 57.15,26.67
N$88  (via drill 1.02)
  other vias: 54.61,26.67
N$89  (via drill 1.02)
  other vias: 52.07,26.67
N$90  (via drill 1.02)
  other vias: 49.53,26.67
N$91  (via drill 1.02)
  other vias: 46.99,26.67
N$98  (via drill 1.02)
  other vias: 34.29,31.75
N$99  (via drill 1.02)
  other vias: 31.75,31.75
N$100  (via drill 1.02)
  other vias: 36.83,34.29
N$101  (via drill 1.02)
  other vias: 34.29,34.29
N$102  (via drill 1.02)
  other vias: 59.69,29.21
N$103  (via drill 1.02)
  other vias: 57.15,29.21
N$104  (via drill 1.02)
  other vias: 54.61,29.21
N$105  (via drill 1.02)
  other vias: 52.07,29.21
N$106  (via drill 1.02)
  other vias: 49.53,29.21
N$107  (via drill 1.02)
  other vias: 46.99,29.21
N$108  (via drill 1.02)
  other vias: 44.45,29.21
N$109  (via drill 1.02)
  other vias: 41.91,29.21
N$110  (via drill 1.02)
  other vias: 39.37,29.21
N$111  (via drill 1.02)
  other vias: 31.75,34.29
N$112  (via drill 1.02)
  other vias: 41.91,26.67
N$113  (via drill 1.02)
  other vias: 59.69,24.13
N$114  (via drill 1.02)
  other vias: 36.83,36.83
N$115  (via drill 1.02)
  other vias: 34.29,36.83
N$116  (via drill 1.02)
  other vias: 31.75,36.83
N$117  (via drill 1.02)
  other vias: 36.83,39.37
N$118  (via drill 1.02)
  other vias: 59.69,31.75
N$119  (via drill 1.02)
  other vias: 57.15,31.75
N$120  (via drill 1.02)
  other vias: 54.61,31.75
N$121  (via drill 1.02)
  other vias: 52.07,31.75
N$122  (via drill 1.02)
  other vias: 49.53,31.75
N$123  (via drill 1.02)
  other vias: 46.99,31.75
N$124  (via drill 1.02)
  other vias: 44.45,31.75
N$125  (via drill 1.02)
  other vias: 41.91,31.75
N$126  (via drill 1.02)
  other vias: 39.37,31.75
N$127  (via drill 1.02)
  other vias: 34.29,39.37
N$128  (via drill 1.02)
  other vias: 41.91,24.13
N$129  (via drill 1.02)
  other vias: 59.69,21.59
N$130  (via drill 1.02)
  other vias: 31.75,39.37
N$131
  Top 0.305: LED7.A R7.2
N$134  (via drill 1.02)
  other vias: 59.69,34.29
N$135  (via drill 1.02)
  other vias: 57.15,34.29
N$136  (via drill 1.02)
  other vias: 54.61,34.29
N$137  (via drill 1.02)
  other vias: 52.07,34.29
N$138  (via drill 1.02)
  other vias: 49.53,34.29
N$139  (via drill 1.02)
  other vias: 46.99,34.29
N$140  (via drill 1.02)
  other vias: 44.45,34.29
N$141  (via drill 1.02)
  other vias: 41.91,34.29
N$142  (via drill 1.02)
  other vias: 39.37,34.29
N$144  (via drill 1.02)
  other vias: 41.91,21.59
N$145  (via drill 1.02)
  other vias: 44.45,26.67
N$150  (via drill 1.02)
  other vias: 59.69,36.83
N$151  (via drill 1.02)
  other vias: 57.15,36.83
N$152  (via drill 1.02)
  other vias: 54.61,36.83
N$153  (via drill 1.02)
  other vias: 52.07,36.83
N$154  (via drill 1.02)
  other vias: 49.53,36.83
N$155  (via drill 1.02)
  other vias: 46.99,36.83
N$156  (via drill 1.02)
  other vias: 44.45,36.83
N$157  (via drill 1.02)
  other vias: 41.91,36.83
N$158  (via drill 1.02)
  other vias: 39.37,36.83
N$160  (via drill 1.02)
  other vias: 39.37,26.67
N$161  (via drill 1.02)
  other vias: 52.07,24.13
N$166  (via drill 1.02)
  other vias: 59.69,39.37
N$167  (via drill 1.02)
  other vias: 57.15,39.37
N$168  (via drill 1.02)
  other vias: 54.61,39.37
N$169  (via drill 1.02)
  other vias: 52.07,39.37
N$170  (via drill 1.02)
  other vias: 49.53,39.37
N$171  (via drill 1.02)
  other vias: 46.99,39.37
N$172  (via drill 1.02)
  other vias: 44.45,39.37
N$173  (via drill 1.02)
  other vias: 41.91,39.37
N$174  (via drill 1.02)
  other vias: 39.37,39.37
N$176  (via drill 1.02)
  other vias: 39.37,24.13
N$177  (via drill 1.02)
  other vias: 46.99,24.13
N$182  (via drill 1.02)
  other vias: 62.23,13.97
N$183  (via drill 1.02)
  other vias: 62.23,16.51
N$184  (via drill 1.02)
  other vias: 62.23,19.05
N$185  (via drill 1.02)
  other vias: 62.23,21.59
N$186  (via drill 1.02)
  other vias: 62.23,24.13
N$187  (via drill 1.02)
  other vias: 62.23,26.67
N$188  (via drill 1.02)
  other vias: 62.23,29.21
N$189  (via drill 1.02)
  other vias: 62.23,31.75
N$190  (via drill 1.02)
  other vias: 62.23,34.29
N$191  (via drill 1.02)
  other vias: 62.23,36.83
N$192  (via drill 1.02)
  other vias: 64.77,39.37
N$193  (via drill 1.02)
  other vias: 64.77,13.97
N$194  (via drill 1.02)
  other vias: 64.77,16.51
N$195  (via drill 1.02)
  other vias: 64.77,19.05
N$196  (via drill 1.02)
  other vias: 64.77,21.59
N$197  (via drill 1.02)
  other vias: 64.77,24.13
N$198  (via drill 1.02)
  other vias: 64.77,26.67
N$199  (via drill 1.02)
  other vias: 64.77,29.21
N$200  (via drill 1.02)
  other vias: 64.77,31.75
N$201  (via drill 1.02)
  other vias: 64.77,34.29
N$202  (via drill 1.02)
  other vias: 64.77,36.83
N$203  (via drill 1.02)
  other vias: 62.23,39.37
N$321
  Top 0.305: R11.2 R10.1 C10.1
N$322
  Top 0.203: U1.1 13.97,47.5 13.97,48.01 12.45,49.53 12.45,50.16 11.05,51.56 R14.2
N$323
  Top 0.305: R5.1 LED5.C
N$325
  Top 0.305: R6.1 LED6.C
N$327
  Top 0.305: R4.1 LED4.C
N$328
  Top 0.305: R3.1 LED3.C
N$329
  Top 0.305: R2.1 LED2.C
N$330
  Top 0.305: R1.1 LED1.C
N$332
  Top 0.305: U2.P$12 2.79,26.92 2.29,27.43 2.29,31.75 R8.2
RESET  (via drill 0.5)
  Top 0.254: D1.3 19.86,34.12 19.81,34.16 v19.81,33.27
  Top 0.305: 23.88,2.92 v23.88,4.83
  Top 0.406: S1.3 23.88,2.92 S1.4 27.18,2.54 H1.1
  Bottom 0.305: v23.88,4.83 18.8,9.91 18.8,32.26 v19.81,33.27
  Bottom 0.61: H1.1 SP1.1
RXIN  (via drill 0.5)
  Top 0.203: v13.21,41.15 13.21,41.66 12.83,42.04 12.83,42.93 12.45,43.31 12.45,44.07 11.96,44.55 U1.6
  Top 0.305: R11.1 19.81,25.65 18.16,27.3 U2.P$2
  Bottom 0.305: v13.21,41.15 19.81,41.15 20.83,40.13 20.83,35.81 20.32,35.31 17.53,35.31 16.76,34.54 16.76,31.5 14.22,28.96 13.97,28.7 U2.P$2
RXIP  (via drill 0.5)
  Top 0.203: v13.72,42.42 13.72,42.8 12.95,43.56 12.95,44.32 12.36,44.92 U1.5
  Top 0.305: U2.P$1 18.54,28.57 19.94,27.18 R10.2
  Bottom 0.305: v13.72,42.42 19.56,42.42 21.59,40.39 21.59,35.56 20.57,34.54 18.03,34.54 17.53,34.04 17.53,29.57 U2.P$1
RXLED
  Top 0.203: U1.72 20.47,41.24 21.34,40.39 21.34,39.88 22.35,38.86 R2.2
SEN
  Top 0.203: Q1.3 1.78,47.07 1.52,46.74 1.52,43.69 1.78,43.43 R16.1 2.79,42.93 2.79,40.89 3.25,40.44 U1.31
SPDLED
  Top 0.203: U1.67 19.18,39.24 19.56,38.86 20.07,38.86 20.83,38.1 20.83,37.59 21.34,37.08 21.34,36.32 21.84,35.81 21.84,35.05 R5.2
TXLED
  Top 0.203: U1.73 20.83,41.64 22.1,40.39 R1.2
TXON  (via drill 0.5)
  Top 0.203: U1.9 10.76,42.84 9.65,41.73 9.65,37.97 v10.67,36.96
  Top 0.305: U2.P$6 18.16,22.23 19.81,20.57 R13.1
  Bottom 0.305: v10.67,36.96 10.67,36.58 13.21,34.04 13.21,30.1 10.79,27.69 10.79,24 12.57,22.23 U2.P$6
TXOP  (via drill 0.5)
  Top 0.203: v12.06,36.96 10.16,38.86 10.16,41.4 11.16,42.4 U1.8
  Top 0.305: U2.P$5 18.41,23.5 19.81,22.1 R12.2
  Bottom 0.305: v12.06,36.96 13.97,35.05 13.97,29.72 11.81,27.56 11.81,24.89 13.21,23.5 U2.P$5
VCC3V3
  Bottom 0.61: H1.2 SP1.2
VIN
  Bottom 0.813: H1.6 SP1.6 45.72,8.64 44.7,9.65 29.59,9.65 28.83,10.41 28.83,17.78 27.56,19.05 JP1.4
XTLN
  Top 0.203: U1.75 18.31,42.44 19.56,43.69 R15.2
  Top 0.305: R15.2 C13.1 19.56,49.53 X1.2
XTLP
  Top 0.203: U1.76 17.18,42.84 18.03,43.69 R15.1
  Top 0.305: X1.1 16.38,50.16 18.03,48.51 C12.1 R15.1

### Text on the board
tPlace: A | GND | D12 | D10 | D8 | D6 | D4 | D2 | D0 | REF | D13 | D11 | D9 | D7 | D5 | D3 | D1 | 5V | (D2INT) | TX | WIZ | RST | RX | COL | FDX | 100 | LNK | D2INT | ! | VIN | - + | PoE | 7-48V | GND | www.freetronics.com | GND | freetronics | Freetronics Ethernet Shield v1.1 | 3V3 | GND | VIN | A1 | A3 | A5 | RST | 5V | GND | A0 | A2 | A4 | PWR | RESET
bPlace: www.freetronics.com/ethernet-shield | A | GND | D12 | D10 | D8 | D6 | D4 | D2 | D0 | REF | D13 | D11 | D9 | D7 | D5 | D3 | D1 | freetronics | 5V | (c) 2010 Freetronics | SKU: SH-ETHERNET | GND | 3V3 | GND | VIN | A1 | A3 | A5 | RST | 5V | GND | A0 | A2 | A4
